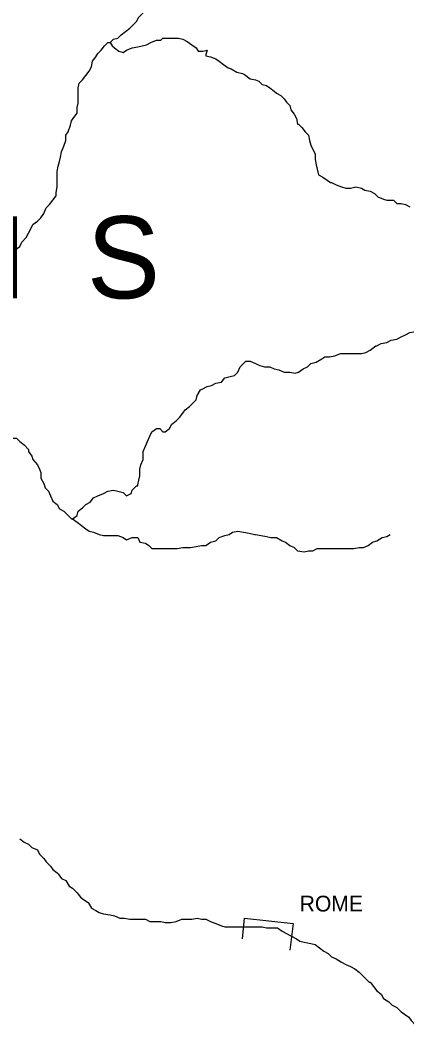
# Model space of a CAD drawing. Extents: x 0 to 34, y 0 to 22.
# Drawn here: x 4.378 to 4.856, y 16.039 to 17.302 of the extents above; entities that cross this region are included whole.
import ezdxf

# ---------------------------------------------------------------- set-up
doc = ezdxf.new("R2010")
doc.units = 0
doc.layers.add('Default', color=7, linetype='Continuous')
doc.layers.add('TR_Turning_Path1', color=7, linetype='Continuous')

msp = doc.modelspace()

# ---------------------------------------------------------------- linework, layer by layer
at = {"layer": 'Default'}
for points in [[(4.5215, 17.3004), (4.5242, 17.3059), (4.5297, 17.3113), (4.5324, 17.3154), (4.5365, 17.3209), (4.5406, 17.3263), (4.5447, 17.3318), (4.5488, 17.3359), (4.5515, 17.3427), (4.5569, 17.3468), (4.5597, 17.3522), (4.5638, 17.3577), (4.5665, 17.3618), (4.5719, 17.3686), (4.5733, 17.3727), (4.576, 17.3781), (4.5788, 17.3822), (4.5788, 17.3836)], [(4.4888, 17.2745), (4.4929, 17.2786), (4.4983, 17.28), (4.5024, 17.2841), (4.5079, 17.2882), (4.5133, 17.2922), (4.516, 17.295), (4.5215, 17.3004), (4.5215, 17.3004)], [(4.422, 17.0891), (4.4233, 17.0959), (4.4233, 17.1014), (4.4233, 17.1082), (4.4233, 17.115), (4.4247, 17.1218), (4.4261, 17.1273), (4.4274, 17.1327), (4.4288, 17.1395), (4.4315, 17.1464), (4.4342, 17.1532), (4.4342, 17.16), (4.437, 17.1641), (4.4397, 17.1723), (4.441, 17.1777), (4.4438, 17.1818), (4.4479, 17.1873), (4.4479, 17.1941), (4.4492, 17.1995), (4.4492, 17.2064), (4.4492, 17.2132), (4.4492, 17.2186), (4.4506, 17.2241), (4.4547, 17.2282), (4.4588, 17.2336), (4.4629, 17.2391), (4.4656, 17.2445), (4.467, 17.2513), (4.471, 17.2568), (4.4738, 17.2609), (4.4779, 17.265), (4.482, 17.2704), (4.486, 17.2745), (4.486, 17.2745), (4.4888, 17.2745)], [(4.4888, 17.2745), (4.4915, 17.2704), (4.4942, 17.2677)], [(4.4942, 17.2677), (4.4997, 17.2636), (4.5051, 17.2623), (4.5092, 17.265), (4.516, 17.2677), (4.5229, 17.2691), (4.5283, 17.2704), (4.5338, 17.2718), (4.5392, 17.2745), (4.546, 17.2772), (4.5515, 17.2772), (4.5542, 17.28), (4.561, 17.28), (4.5665, 17.28), (4.5733, 17.28), (4.5788, 17.2786), (4.5842, 17.2759), (4.5897, 17.2718), (4.5951, 17.2677), (4.5978, 17.2636), (4.6033, 17.2636), (4.6088, 17.265), (4.6074, 17.2595), (4.6074, 17.2582)], [(4.6074, 17.2582), (4.6128, 17.2568), (4.6197, 17.2541), (4.6237, 17.2513), (4.6292, 17.2473), (4.6347, 17.2432), (4.6387, 17.2418), (4.6456, 17.2377), (4.6524, 17.2363), (4.6551, 17.235), (4.6619, 17.2295), (4.6687, 17.2282), (4.6728, 17.2268), (4.6769, 17.2227), (4.6824, 17.2213), (4.6865, 17.2186), (4.6919, 17.2145), (4.6946, 17.2118), (4.7001, 17.2091), (4.7042, 17.205), (4.7069, 17.2009), (4.711, 17.1968), (4.7124, 17.1914), (4.7165, 17.1859), (4.7192, 17.1804), (4.7206, 17.1736), (4.7219, 17.1736)], [(4.7219, 17.1736), (4.726, 17.1695), (4.7301, 17.1641), (4.7342, 17.16), (4.7355, 17.1532), (4.7369, 17.1477), (4.7396, 17.1423), (4.7424, 17.1368), (4.7424, 17.13), (4.7437, 17.1232), (4.7451, 17.1177), (4.7465, 17.1109), (4.7519, 17.1082), (4.7574, 17.1041), (4.7615, 17.1014), (4.7615, 17.1014), (4.7628, 17.1014)], [(4.7628, 17.1014), (4.7683, 17.0986), (4.7751, 17.0959), (4.7805, 17.0946), (4.786, 17.0946), (4.7928, 17.0959), (4.7996, 17.0946), (4.8037, 17.0918), (4.8105, 17.0905), (4.816, 17.0877), (4.8201, 17.0836), (4.8269, 17.0809), (4.831, 17.0796), (4.8392, 17.0796), (4.8433, 17.0755), (4.8487, 17.0755), (4.8542, 17.0741), (4.8596, 17.0714)], [(4.3415, 17.0087), (4.3483, 17.0127), (4.3524, 17.0141), (4.3606, 17.0141), (4.3661, 17.0141), (4.3715, 17.0182), (4.377, 17.0223), (4.3797, 17.0277), (4.3851, 17.0332), (4.3879, 17.0387), (4.3906, 17.0441), (4.3933, 17.0496), (4.3988, 17.0536), (4.4029, 17.0577), (4.407, 17.0632), (4.4097, 17.07), (4.4138, 17.0741), (4.4179, 17.0796), (4.422, 17.085), (4.422, 17.0891)], [(4.8187, 16.8996), (4.8242, 16.9023), (4.831, 16.9037), (4.8364, 16.9064), (4.8433, 16.9078), (4.8487, 16.9105), (4.8542, 16.9132), (4.8596, 16.9159), (4.8664, 16.9173), (4.8733, 16.9187), (4.8787, 16.9214), (4.8842, 16.9269), (4.8883, 16.9241), (4.8896, 16.9241)], [(4.6565, 16.8805), (4.6619, 16.8805), (4.6687, 16.8778), (4.6742, 16.875), (4.6796, 16.8737), (4.6865, 16.8737), (4.6919, 16.8709), (4.6974, 16.8696), (4.7042, 16.8669), (4.711, 16.8669), (4.7178, 16.8655), (4.7219, 16.8669), (4.7274, 16.8709), (4.7328, 16.8737), (4.7369, 16.8778), (4.7437, 16.8791), (4.7505, 16.8832), (4.7546, 16.8859), (4.7601, 16.8859), (4.7669, 16.8873), (4.7737, 16.89), (4.7792, 16.89), (4.786, 16.89), (4.7928, 16.89), (4.7996, 16.89), (4.8051, 16.8914), (4.8105, 16.8941), (4.816, 16.8982), (4.8174, 16.8996), (4.8187, 16.8996)], [(4.6033, 16.8464), (4.6088, 16.8491), (4.6142, 16.8505), (4.6197, 16.8532), (4.6265, 16.8546), (4.6306, 16.86), (4.6374, 16.8614), (4.6428, 16.8628), (4.6469, 16.8669), (4.6497, 16.8737), (4.6537, 16.8778), (4.6565, 16.8805)], [(4.5569, 16.7932), (4.5624, 16.7973), (4.5651, 16.8028), (4.5706, 16.8069), (4.5747, 16.811), (4.5788, 16.8164), (4.5815, 16.8205), (4.5869, 16.8246), (4.591, 16.8287), (4.5951, 16.8328), (4.5965, 16.8382), (4.6006, 16.845), (4.6033, 16.8464)], [(4.5229, 16.7278), (4.5242, 16.7332), (4.5256, 16.7387), (4.5256, 16.7469), (4.5269, 16.7523), (4.5297, 16.7591), (4.5297, 16.7632), (4.5297, 16.7687), (4.5324, 16.7755), (4.5351, 16.781), (4.5379, 16.7878), (4.5406, 16.7932), (4.546, 16.7973), (4.5501, 16.7973), (4.5542, 16.7932), (4.5569, 16.7932), (4.5569, 16.7932)], [(4.287, 16.7687), (4.2924, 16.7687), (4.3006, 16.7687), (4.3061, 16.7687), (4.3115, 16.7673), (4.3183, 16.7687), (4.3252, 16.7714), (4.3306, 16.7741), (4.3361, 16.7769), (4.3415, 16.7796), (4.3483, 16.781), (4.3538, 16.7837), (4.3606, 16.7851), (4.3674, 16.7851), (4.3729, 16.7851), (4.377, 16.781), (4.3824, 16.7769), (4.3879, 16.7714), (4.3879, 16.7687)], [(4.3879, 16.7687), (4.392, 16.7632), (4.3933, 16.7591), (4.3988, 16.7523), (4.4015, 16.7469), (4.4029, 16.7428), (4.4029, 16.736), (4.407, 16.7292), (4.4083, 16.7237), (4.4124, 16.7196), (4.4151, 16.7142), (4.4179, 16.7073), (4.4233, 16.7032), (4.4261, 16.6978), (4.4315, 16.6951), (4.437, 16.6896), (4.441, 16.6855), (4.4424, 16.6855), (4.4424, 16.6855)], [(4.4424, 16.6855), (4.4479, 16.6896), (4.4492, 16.6951), (4.4547, 16.6992), (4.4588, 16.7032), (4.4642, 16.706), (4.4683, 16.7114), (4.4738, 16.7142), (4.4806, 16.7169), (4.486, 16.7196), (4.4929, 16.721), (4.4983, 16.7196), (4.5051, 16.7182), (4.5092, 16.7142), (4.5147, 16.7169), (4.516, 16.721), (4.5215, 16.7264), (4.5229, 16.7264), (4.5229, 16.7278)], [(4.4424, 16.6855), (4.4479, 16.6814), (4.4533, 16.6773), (4.4588, 16.6733), (4.4629, 16.6705), (4.4683, 16.6692), (4.4751, 16.6664), (4.4806, 16.6651), (4.486, 16.6651), (4.4929, 16.6651), (4.4983, 16.6651), (4.5051, 16.6623), (4.5092, 16.6596), (4.516, 16.6623), (4.5229, 16.6623), (4.5256, 16.6569), (4.5324, 16.6555), (4.5365, 16.6528), (4.5406, 16.6487), (4.5474, 16.6487), (4.5542, 16.6487), (4.5597, 16.6487), (4.5665, 16.6487), (4.5719, 16.6487), (4.5788, 16.6501), (4.5815, 16.6501)], [(4.5815, 16.6501), (4.5883, 16.6501), (4.5951, 16.6514), (4.6019, 16.6528), (4.6074, 16.6528), (4.6128, 16.6569), (4.6197, 16.6583), (4.6237, 16.6623), (4.6306, 16.6651), (4.636, 16.6664), (4.6401, 16.6692), (4.6469, 16.6705), (4.6537, 16.6692), (4.6606, 16.6678), (4.6674, 16.6664), (4.6687, 16.6664)], [(4.6687, 16.6664), (4.6756, 16.6651), (4.6824, 16.6637), (4.6878, 16.6623), (4.6946, 16.6623), (4.7015, 16.6583), (4.7056, 16.6569), (4.711, 16.6528), (4.7165, 16.6501), (4.7206, 16.646), (4.7287, 16.6446), (4.7342, 16.646), (4.7396, 16.646), (4.7451, 16.6487), (4.7451, 16.6487), (4.7451, 16.6487)], [(4.7451, 16.6487), (4.7505, 16.6487), (4.7587, 16.6487), (4.7655, 16.6487), (4.771, 16.6487), (4.7765, 16.6487), (4.7833, 16.6487), (4.7901, 16.6487), (4.7969, 16.6501), (4.8024, 16.6501), (4.8078, 16.6528), (4.8133, 16.6569), (4.8187, 16.6583), (4.8255, 16.6623), (4.831, 16.6637), (4.8351, 16.6664), (4.8351, 16.6664)], [(4.377, 16.2901), (4.3824, 16.286), (4.3879, 16.2833), (4.392, 16.2792), (4.3988, 16.2765), (4.4015, 16.271), (4.407, 16.2656), (4.4097, 16.2615), (4.4151, 16.256), (4.4179, 16.252), (4.4233, 16.2479), (4.4233, 16.2479), (4.4247, 16.2465)], [(4.4247, 16.2465), (4.4288, 16.241), (4.4342, 16.2383), (4.4383, 16.2315), (4.4424, 16.2288), (4.4479, 16.2233), (4.452, 16.2179), (4.456, 16.2151), (4.4615, 16.2111), (4.4656, 16.2042), (4.471, 16.2015), (4.4751, 16.1988), (4.4806, 16.1974), (4.4888, 16.1961), (4.4942, 16.1947), (4.501, 16.192), (4.5065, 16.192), (4.5133, 16.1906), (4.5188, 16.1906), (4.5256, 16.1906), (4.5324, 16.1906), (4.5379, 16.1879), (4.546, 16.1879), (4.5515, 16.1879), (4.5569, 16.1865), (4.5638, 16.1865), (4.5706, 16.1879), (4.5774, 16.1906), (4.5815, 16.1906), (4.5897, 16.1906), (4.5965, 16.192), (4.6019, 16.1906), (4.6074, 16.1906), (4.6128, 16.1879), (4.6197, 16.1851), (4.6265, 16.1824), (4.6306, 16.1811), (4.6374, 16.1811), (4.6442, 16.1811), (4.6524, 16.1811), (4.6565, 16.1811), (4.6633, 16.1811), (4.6701, 16.1811), (4.6769, 16.1811), (4.6824, 16.1797), (4.6878, 16.1797), (4.6946, 16.1797), (4.696, 16.1797)], [(4.6524, 16.1661), (4.6551, 16.192), (4.7151, 16.1851), (4.711, 16.1524)], [(4.696, 16.1797), (4.7015, 16.1756), (4.7069, 16.1729), (4.7124, 16.1702), (4.7192, 16.1661), (4.7233, 16.1633), (4.7287, 16.162), (4.7369, 16.1606), (4.7424, 16.1592), (4.7478, 16.1552), (4.7533, 16.1511), (4.7587, 16.1483), (4.7628, 16.1442), (4.7683, 16.1415), (4.7751, 16.1374), (4.7805, 16.1347), (4.786, 16.132), (4.7914, 16.1292), (4.7969, 16.1252), (4.801, 16.1211), (4.8051, 16.117), (4.8092, 16.1129), (4.8092, 16.1129), (4.8105, 16.1129)], [(4.8105, 16.1129), (4.8146, 16.1074), (4.8187, 16.102), (4.8242, 16.0979), (4.8269, 16.0924), (4.8337, 16.0883), (4.8378, 16.0843), (4.8433, 16.0815), (4.8487, 16.0761), (4.8528, 16.0733), (4.8583, 16.0693), (4.861, 16.0652), (4.8664, 16.0597), (4.8705, 16.0556), (4.876, 16.0515), (4.8801, 16.0488), (4.8855, 16.0447), (4.891, 16.0406), (4.8923, 16.0406), (4.8937, 16.0393)]]:
    msp.add_lwpolyline(points, dxfattribs=at)

# ---------------------------------------------------------------- texts
msp.add_text('ROME', height=0.0195, dxfattribs=at).set_placement((4.7233, 16.2001))
at = {"layer": 'TR_Turning_Path1'}
msp.add_text('A  D  A  M  S', height=0.101489, dxfattribs=at).set_placement((3.7663, 16.9582))

doc.saveas('drawing.dxf')
